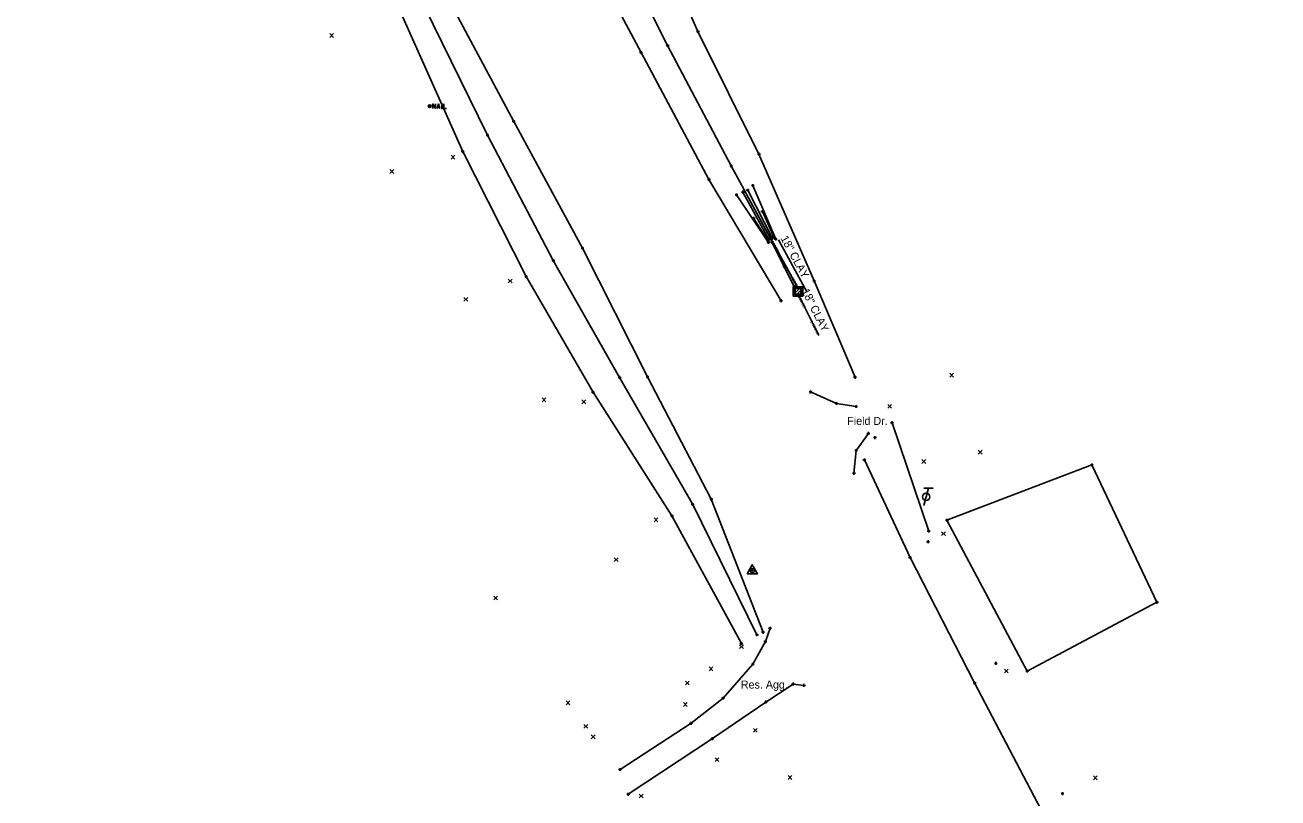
# Model space of a CAD drawing. Extents: x 2298098 to 2302860, y 557788 to 564251.
# Drawn here: x 2299686.7 to 2300125, y 560704.7 to 560975.2 of the extents above; entities that cross this region are included whole.
import ezdxf

# ---------------------------------------------------------------- set-up
doc = ezdxf.new("R2010")
doc.units = 0
for name, color, linetype in [('BD_X_Building', 7, 'Continuous'), ('DR_X_Cells', 7, 'Continuous'), ('DR_X_Ditch', 7, 'Continuous'), ('DR_X_Elev_Flow', 7, 'Continuous'), ('DR_X_Storm_Sewer', 7, 'Continuous'), ('DR_X_Text', 7, 'Continuous'), ('GK_Drainage_Nodes', 7, 'Continuous'), ('PV_X_Curb', 7, 'Continuous'), ('PV_X_Driveway', 7, 'Continuous'), ('PV_X_Text', 7, 'Continuous'), ('SC_Scratch1', 7, 'Continuous'), ('SV_P_Aerial_Targets', 7, 'Continuous'), ('SV_X_Break_Lines', 7, 'Continuous'), ('SV_X_Control_Cells_Found', 7, 'Continuous'), ('SV_X_Random_Point', 7, 'Continuous'), ('SV_X_Shot_Marker', 7, 'Continuous'), ('UT_X_Telecom_Cells', 7, 'Continuous')]:
    doc.layers.add(name, color=color, linetype=linetype)

msp = doc.modelspace()

# ---------------------------------------------------------------- linework, layer by layer
at = {"layer": 'BD_X_Building'}
msp.add_lwpolyline([(2300037.29, 560749.13), (2300082.72, 560773.18), (2300059.94, 560821.31), (2300009.23, 560801.93)], close=True, dxfattribs=at)
at = {"layer": 'DR_X_Cells'}
for p, q in [((2299955.98, 560881.35), (2299957.74, 560883.11)), ((2299955.98, 560882.48), (2299956.61, 560883.11)), ((2299956.58, 560880.82), (2299958.27, 560882.51)), ((2299957.71, 560880.82), (2299958.27, 560881.38))]:
    msp.add_line(p, q, dxfattribs=at)
for points in [[(2299955.46, 560883.63), (2299958.79, 560883.63), (2299958.79, 560880.3), (2299955.46, 560880.3)], [(2299955.98, 560883.11), (2299958.27, 560883.11), (2299958.27, 560880.82), (2299955.98, 560880.82)], [(2299956.13, 560882.96), (2299958.12, 560882.96), (2299958.12, 560880.97), (2299956.13, 560880.97)]]:
    msp.add_lwpolyline(points, close=True, dxfattribs=at)
at = {"layer": 'DR_X_Ditch'}
for p, q in [((2299946.86, 560900.2), (2299937.85, 560916.76)), ((2299939.52, 560917.42), (2299939.52, 560917.42)), ((2299948.12, 560900.69), (2299939.52, 560917.42))]:
    msp.add_line(p, q, dxfattribs=at)
for points in [[(2299947.33, 560900.77), (2299933.75, 560925.88), (2299911.49, 560968.04), (2299888.52, 561013.62), (2299864.88, 561059.66), (2299843.49, 561104.65), (2299821.62, 561147.64), (2299797.59, 561193.32), (2299770.88, 561234.4), (2299749.36, 561272.5)], [(2299689.17, 561239.02), (2299710.05, 561199.51), (2299732.46, 561156.76), (2299754.64, 561114.4), (2299777.04, 561070.1), (2299803.82, 561025.63), (2299826.29, 560981.81), (2299848.46, 560936.68), (2299871.48, 560892.79), (2299894.72, 560851.89), (2299920.28, 560807.43), (2299942.76, 560761.82)], [(2299955.8, 560883.68), (2299947.98, 560899.25)]]:
    msp.add_lwpolyline(points, dxfattribs=at)
at = {"layer": 'DR_X_Elev_Flow'}
for p, q in [((2299947.19, 560900.31), (2299948.19, 560900.31)), ((2299947.69, 560900.81), (2299947.69, 560899.81)), ((2299947.69, 560900.31), (2299947.69, 560900.31)), ((2299951.76, 560890.74), (2299952.76, 560890.74)), ((2299952.26, 560891.24), (2299952.26, 560890.24)), ((2299952.26, 560890.74), (2299952.26, 560890.74))]:
    msp.add_line(p, q, dxfattribs=at)
at = {"layer": 'DR_X_Storm_Sewer'}
for p, q in [((2299947.69, 560900.31), (2299957.12, 560882.96)), ((2299957.12, 560880.97), (2299964.37, 560866.53))]:
    msp.add_line(p, q, dxfattribs=at)
at = {"layer": 'DR_X_Text'}
msp.add_line((2299960.21, 560881.79), (2299950.29, 560900.02), dxfattribs=at)
at = {"layer": 'GK_Drainage_Nodes'}
for p, q in [((2299957.12, 560883.63), (2299957.12, 560883.63)), ((2299956.13, 560881.96), (2299956.13, 560881.96)), ((2299957.12, 560882.96), (2299957.12, 560882.96)), ((2299957.12, 560881.96), (2299957.12, 560881.96)), ((2299957.12, 560881.96), (2299957.12, 560881.96)), ((2299957.12, 560881.96), (2299957.12, 560881.96)), ((2299957.12, 560880.97), (2299957.12, 560880.97)), ((2299957.12, 560880.3), (2299957.12, 560880.3)), ((2299958.12, 560881.96), (2299958.12, 560881.96))]:
    msp.add_line(p, q, dxfattribs=at)
at = {"layer": 'PV_X_Curb'}
msp.add_line((2299935.62, 560915.79), (2299935.62, 560915.79), dxfattribs=at)
for points in [[(2299941.3, 560919.05), (2299949.32, 560900.24)], [(2299946.77, 560899.11), (2299935.62, 560915.79)]]:
    msp.add_lwpolyline(points, dxfattribs=at)
at = {"layer": 'PV_X_Driveway'}
for points in [[(2299961.53, 560846.8), (2299970.58, 560842.74), (2299977.47, 560841.68)], [(2299976.68, 560818.33), (2299977.47, 560826.3), (2299981.76, 560832.31)], [(2299947.34, 560764.07), (2299945.7, 560759.43), (2299941.3, 560751.53), (2299930.9, 560739.64), (2299919.71, 560730.84), (2299894.85, 560714.65)], [(2299897.73, 560706.01), (2299927.17, 560725.49), (2299945.85, 560738.28), (2299955.39, 560744.58), (2299959.21, 560744.09)]]:
    msp.add_lwpolyline(points, dxfattribs=at)
at = {"layer": 'SV_P_Aerial_Targets'}
msp.add_lwpolyline([(2299939.32, 560783.09), (2299942.92, 560783.09), (2299941.12, 560786.31)], close=True, dxfattribs=at)
for radius in [0.7, 0.16]:
    msp.add_circle((2299941.12, 560784.25), radius, dxfattribs=at)
at = {"layer": 'SV_X_Break_Lines'}
for points in [[(2299977.08, 560851.92), (2299962.79, 560885.63), (2299943.44, 560930.04), (2299922.12, 560972.96), (2299899.62, 561024.1), (2299876.86, 561061.88), (2299856.06, 561110.09), (2299831.14, 561154.42), (2299808.16, 561196.66), (2299781, 561237.26), (2299752.42, 561274.51)], [(2299743.18, 561269.26), (2299761.95, 561229.81), (2299785.6, 561185.67), (2299809.04, 561141.23), (2299831.82, 561097.39), (2299855.54, 561053.53), (2299878.79, 561009.46), (2299902.19, 560965.55), (2299925.95, 560921.19), (2299951.18, 560878.72)], [(2299692.06, 561241.01), (2299717.5, 561205.23), (2299740.15, 561162.59), (2299763.02, 561119.04), (2299785.96, 561075.58), (2299810.78, 561030.53), (2299833.61, 560986.47), (2299857.66, 560941.45), (2299881.73, 560897.12), (2299904.47, 560852.04), (2299926.78, 560809.23), (2299944.9, 560762.68)], [(2299937.32, 560758.74), (2299913.01, 560803.44), (2299885.4, 560846.69), (2299862.02, 560887.18), (2299839.82, 560930.89), (2299818.82, 560977.94), (2299795.83, 561022.36), (2299768.22, 561073.24), (2299750.41, 561112.94), (2299723.48, 561156), (2299704.62, 561197.18), (2299686.67, 561238.25)], [(2299948.81, 560900.74), (2299944.67, 560909.91)], [(2299946.68, 560899.68), (2299941.59, 560907.59)], [(2300002.85, 560798.07), (2299990.04, 560836.02)], [(2299980.36, 560823), (2299996.31, 560788.88), (2300018.92, 560744.96), (2300042.25, 560700.52), (2300065.09, 560656.83), (2300088.55, 560612.83), (2300119.49, 560571.33), (2300125.05, 560565.91)]]:
    msp.add_lwpolyline(points, dxfattribs=at)
at = {"layer": 'SV_X_Control_Cells_Found'}
for p, q in [((2299827.92, 560947.16), (2299828.62, 560946.45)), ((2299827.92, 560946.45), (2299828.62, 560947.16))]:
    msp.add_line(p, q, dxfattribs=at)
for points in [[(2299829.36, 560946), (2299829.36, 560947.6), (2299830.3, 560946), (2299830.3, 560947.6)], [(2299830.81, 560946), (2299831.31, 560947.6), (2299831.8, 560946)], [(2299831.68, 560946.38), (2299830.93, 560946.38)], [(2299832.31, 560947.6), (2299832.71, 560947.6)], [(2299832.31, 560946), (2299832.71, 560946)], [(2299832.51, 560946), (2299832.51, 560947.6)], [(2299833.21, 560947.6), (2299833.21, 560946), (2299834.08, 560946)]]:
    msp.add_lwpolyline(points, dxfattribs=at)
msp.add_circle((2299828.27, 560946.81), 0.5, dxfattribs=at)
at = {"layer": 'SV_X_Random_Point'}
for p, q in [((2299793.28, 560970.88), (2299794.61, 560972.21)), ((2299793.28, 560972.21), (2299794.61, 560970.88)), ((2299835.71, 560928.28), (2299837.04, 560929.61)), ((2299835.71, 560929.61), (2299837.04, 560928.28)), ((2299814.32, 560923.27), (2299815.65, 560924.6)), ((2299814.32, 560924.6), (2299815.65, 560923.27)), ((2299855.76, 560884.94), (2299857.09, 560886.27)), ((2299855.76, 560886.27), (2299857.09, 560884.94)), ((2299840.23, 560878.56), (2299841.56, 560879.89)), ((2299840.23, 560879.89), (2299841.56, 560878.56)), ((2300010.22, 560851.98), (2300011.55, 560853.31)), ((2300010.22, 560853.31), (2300011.55, 560851.98)), ((2299867.58, 560843.36), (2299868.91, 560844.7)), ((2299867.58, 560844.7), (2299868.91, 560843.36)), ((2299881.52, 560842.69), (2299882.85, 560844.02)), ((2299881.52, 560844.02), (2299882.85, 560842.69)), ((2299988.51, 560841.09), (2299989.84, 560842.42)), ((2299988.51, 560842.42), (2299989.84, 560841.09)), ((2300000.48, 560821.78), (2300001.81, 560823.12)), ((2300000.48, 560823.12), (2300001.81, 560821.78)), ((2300020.2, 560825.06), (2300021.54, 560826.4)), ((2300020.2, 560826.4), (2300021.54, 560825.06)), ((2299906.76, 560801.37), (2299908.09, 560802.7)), ((2299906.76, 560802.7), (2299908.09, 560801.37)), ((2300007.36, 560796.54), (2300008.69, 560797.88)), ((2300007.36, 560797.88), (2300008.69, 560796.54)), ((2299892.85, 560787.44), (2299894.18, 560788.77)), ((2299892.85, 560788.77), (2299894.18, 560787.44)), ((2299850.65, 560774.04), (2299851.98, 560775.38)), ((2299850.65, 560775.38), (2299851.98, 560774.04)), ((2299936.7, 560756.97), (2299938.03, 560758.3)), ((2299936.7, 560758.3), (2299938.03, 560756.97)), ((2299926, 560749.25), (2299927.33, 560750.59)), ((2299926, 560750.59), (2299927.33, 560749.25)), ((2300029.33, 560748.46), (2300030.67, 560749.79)), ((2300029.33, 560749.79), (2300030.67, 560748.46)), ((2299917.72, 560744.29), (2299919.06, 560745.62)), ((2299917.72, 560745.62), (2299919.06, 560744.29)), ((2299875.99, 560737.31), (2299877.32, 560738.64)), ((2299875.99, 560738.64), (2299877.32, 560737.31)), ((2299917.03, 560736.74), (2299918.36, 560738.07)), ((2299917.03, 560738.07), (2299918.36, 560736.74)), ((2299882.2, 560729.11), (2299883.53, 560730.45)), ((2299882.2, 560730.45), (2299883.53, 560729.11)), ((2299884.75, 560725.45), (2299886.09, 560726.78)), ((2299884.75, 560726.78), (2299886.09, 560725.45)), ((2299941.53, 560727.72), (2299942.86, 560729.06)), ((2299941.53, 560729.06), (2299942.86, 560727.72)), ((2299928.08, 560717.41), (2299929.41, 560718.74)), ((2299928.08, 560718.74), (2299929.41, 560717.41)), ((2299953.63, 560711.19), (2299954.96, 560712.53)), ((2299953.63, 560712.53), (2299954.96, 560711.19)), ((2300060.49, 560711.07), (2300061.82, 560712.4)), ((2300060.49, 560712.4), (2300061.82, 560711.07)), ((2299901.57, 560704.75), (2299902.91, 560706.08)), ((2299901.57, 560706.08), (2299902.91, 560704.75))]:
    msp.add_line(p, q, dxfattribs=at)
at = {"layer": 'SV_X_Shot_Marker'}
for p, q in [((2299921.62, 560972.96), (2299922.62, 560972.96)), ((2299922.12, 560973.46), (2299922.12, 560972.46)), ((2299922.12, 560972.96), (2299922.12, 560972.96)), ((2299910.99, 560968.04), (2299911.99, 560968.04)), ((2299911.49, 560968.54), (2299911.49, 560967.54)), ((2299911.49, 560968.04), (2299911.49, 560968.04)), ((2299901.69, 560965.55), (2299902.69, 560965.55)), ((2299902.19, 560966.05), (2299902.19, 560965.05)), ((2299902.19, 560965.55), (2299902.19, 560965.55)), ((2299857.16, 560941.45), (2299858.16, 560941.45)), ((2299857.66, 560941.95), (2299857.66, 560940.95)), ((2299857.66, 560941.45), (2299857.66, 560941.45)), ((2299847.96, 560936.68), (2299848.96, 560936.68)), ((2299848.46, 560937.18), (2299848.46, 560936.18)), ((2299848.46, 560936.68), (2299848.46, 560936.68)), ((2299839.32, 560930.89), (2299840.32, 560930.89)), ((2299839.82, 560931.39), (2299839.82, 560930.39)), ((2299839.82, 560930.89), (2299839.82, 560930.89)), ((2299942.94, 560930.04), (2299943.94, 560930.04)), ((2299943.44, 560930.54), (2299943.44, 560929.54)), ((2299943.44, 560930.04), (2299943.44, 560930.04)), ((2299933.25, 560925.88), (2299934.25, 560925.88)), ((2299933.75, 560926.38), (2299933.75, 560925.38)), ((2299933.75, 560925.88), (2299933.75, 560925.88)), ((2299925.45, 560921.19), (2299926.45, 560921.19)), ((2299925.95, 560921.69), (2299925.95, 560920.69)), ((2299925.95, 560921.19), (2299925.95, 560921.19)), ((2299940.8, 560919.05), (2299941.8, 560919.05)), ((2299941.3, 560919.55), (2299941.3, 560918.55)), ((2299941.3, 560919.05), (2299941.3, 560919.05)), ((2299935.12, 560915.79), (2299936.12, 560915.79)), ((2299935.62, 560916.29), (2299935.62, 560915.29)), ((2299935.62, 560915.79), (2299935.62, 560915.79)), ((2299937.35, 560916.76), (2299938.35, 560916.76)), ((2299937.85, 560917.26), (2299937.85, 560916.26)), ((2299937.85, 560916.76), (2299937.85, 560916.76)), ((2299939.02, 560917.42), (2299940.02, 560917.42)), ((2299939.52, 560917.92), (2299939.52, 560916.92)), ((2299939.52, 560917.42), (2299939.52, 560917.42)), ((2299944.17, 560909.91), (2299945.17, 560909.91)), ((2299944.67, 560910.41), (2299944.67, 560909.41)), ((2299944.67, 560909.91), (2299944.67, 560909.91)), ((2299941.09, 560907.59), (2299942.09, 560907.59)), ((2299941.59, 560908.09), (2299941.59, 560907.09)), ((2299941.59, 560907.59), (2299941.59, 560907.59)), ((2299947.33, 560901.27), (2299947.33, 560900.27)), ((2299948.12, 560901.19), (2299948.12, 560900.19)), ((2299948.81, 560901.24), (2299948.81, 560900.24)), ((2299881.23, 560897.12), (2299882.23, 560897.12)), ((2299881.73, 560897.62), (2299881.73, 560896.62)), ((2299881.73, 560897.12), (2299881.73, 560897.12)), ((2299946.18, 560899.68), (2299947.18, 560899.68)), ((2299946.27, 560899.11), (2299947.27, 560899.11)), ((2299946.36, 560900.2), (2299947.36, 560900.2)), ((2299946.68, 560900.18), (2299946.68, 560899.18)), ((2299946.68, 560899.68), (2299946.68, 560899.68)), ((2299946.77, 560899.61), (2299946.77, 560898.61)), ((2299946.77, 560899.11), (2299946.77, 560899.11)), ((2299946.83, 560900.77), (2299947.83, 560900.77)), ((2299946.86, 560900.7), (2299946.86, 560899.7)), ((2299946.86, 560900.2), (2299946.86, 560900.2)), ((2299947.33, 560900.77), (2299947.33, 560900.77)), ((2299947.48, 560899.25), (2299948.48, 560899.25)), ((2299947.62, 560900.69), (2299948.62, 560900.69)), ((2299947.98, 560899.75), (2299947.98, 560898.75)), ((2299947.98, 560899.25), (2299947.98, 560899.25)), ((2299948.12, 560900.69), (2299948.12, 560900.69)), ((2299948.31, 560900.74), (2299949.31, 560900.74)), ((2299948.81, 560900.74), (2299948.81, 560900.74)), ((2299948.82, 560900.24), (2299949.82, 560900.24)), ((2299949.32, 560900.74), (2299949.32, 560899.74)), ((2299949.32, 560900.24), (2299949.32, 560900.24)), ((2299870.98, 560892.79), (2299871.98, 560892.79)), ((2299871.48, 560893.29), (2299871.48, 560892.29)), ((2299871.48, 560892.79), (2299871.48, 560892.79)), ((2299861.52, 560887.18), (2299862.52, 560887.18)), ((2299862.02, 560887.68), (2299862.02, 560886.68)), ((2299862.02, 560887.18), (2299862.02, 560887.18)), ((2299955.3, 560883.68), (2299956.3, 560883.68)), ((2299955.8, 560884.18), (2299955.8, 560883.18)), ((2299955.8, 560883.68), (2299955.8, 560883.68)), ((2299962.29, 560885.63), (2299963.29, 560885.63)), ((2299962.79, 560886.13), (2299962.79, 560885.13)), ((2299962.79, 560885.63), (2299962.79, 560885.63)), ((2299951.18, 560879.22), (2299951.18, 560878.22)), ((2299950.68, 560878.72), (2299951.68, 560878.72)), ((2299951.18, 560878.72), (2299951.18, 560878.72)), ((2299894.22, 560851.89), (2299895.22, 560851.89)), ((2299894.72, 560852.39), (2299894.72, 560851.39)), ((2299894.72, 560851.89), (2299894.72, 560851.89)), ((2299903.97, 560852.04), (2299904.97, 560852.04)), ((2299904.47, 560852.54), (2299904.47, 560851.54)), ((2299904.47, 560852.04), (2299904.47, 560852.04)), ((2299976.58, 560851.92), (2299977.58, 560851.92)), ((2299977.08, 560852.42), (2299977.08, 560851.42)), ((2299977.08, 560851.92), (2299977.08, 560851.92)), ((2299884.9, 560846.69), (2299885.9, 560846.69)), ((2299885.4, 560847.19), (2299885.4, 560846.19)), ((2299885.4, 560846.69), (2299885.4, 560846.69)), ((2299961.03, 560846.8), (2299962.03, 560846.8)), ((2299961.53, 560847.3), (2299961.53, 560846.3)), ((2299961.53, 560846.8), (2299961.53, 560846.8)), ((2299970.08, 560842.74), (2299971.08, 560842.74)), ((2299970.58, 560843.24), (2299970.58, 560842.24)), ((2299970.58, 560842.74), (2299970.58, 560842.74)), ((2299976.97, 560841.68), (2299977.97, 560841.68)), ((2299977.47, 560842.18), (2299977.47, 560841.18)), ((2299977.47, 560841.68), (2299977.47, 560841.68)), ((2299989.54, 560836.02), (2299990.54, 560836.02)), ((2299990.04, 560836.52), (2299990.04, 560835.52)), ((2299990.04, 560836.02), (2299990.04, 560836.02)), ((2299981.26, 560832.31), (2299982.26, 560832.31)), ((2299981.76, 560832.81), (2299981.76, 560831.81)), ((2299981.76, 560832.31), (2299981.76, 560832.31)), ((2299984.05, 560831.32), (2299984.05, 560830.32)), ((2299977.47, 560826.8), (2299977.47, 560825.8)), ((2299983.55, 560830.82), (2299984.55, 560830.82)), ((2299984.05, 560830.82), (2299984.05, 560830.82)), ((2299976.97, 560826.3), (2299977.97, 560826.3)), ((2299977.47, 560826.3), (2299977.47, 560826.3)), ((2299979.86, 560823), (2299980.86, 560823)), ((2299980.36, 560823.5), (2299980.36, 560822.5)), ((2299980.36, 560823), (2299980.36, 560823)), ((2299976.18, 560818.33), (2299977.18, 560818.33)), ((2299976.68, 560818.83), (2299976.68, 560817.83)), ((2299976.68, 560818.33), (2299976.68, 560818.33)), ((2300059.44, 560821.31), (2300060.44, 560821.31)), ((2300059.94, 560821.81), (2300059.94, 560820.81)), ((2300059.94, 560821.31), (2300059.94, 560821.31)), ((2299926.28, 560809.23), (2299927.28, 560809.23)), ((2299926.78, 560809.73), (2299926.78, 560808.73)), ((2299926.78, 560809.23), (2299926.78, 560809.23)), ((2299919.78, 560807.43), (2299920.78, 560807.43)), ((2299920.28, 560807.93), (2299920.28, 560806.93)), ((2299920.28, 560807.43), (2299920.28, 560807.43)), ((2299912.51, 560803.44), (2299913.51, 560803.44)), ((2299913.01, 560803.94), (2299913.01, 560802.94)), ((2299913.01, 560803.44), (2299913.01, 560803.44)), ((2300008.73, 560801.93), (2300009.73, 560801.93)), ((2300009.23, 560802.43), (2300009.23, 560801.43)), ((2300009.23, 560801.93), (2300009.23, 560801.93)), ((2300002.35, 560798.07), (2300003.35, 560798.07)), ((2300002.85, 560798.57), (2300002.85, 560797.57)), ((2300002.85, 560798.07), (2300002.85, 560798.07)), ((2300002.12, 560794.39), (2300003.12, 560794.39)), ((2300002.62, 560794.89), (2300002.62, 560793.89)), ((2300002.62, 560794.39), (2300002.62, 560794.39)), ((2299995.81, 560788.88), (2299996.81, 560788.88)), ((2299996.31, 560789.38), (2299996.31, 560788.38)), ((2299996.31, 560788.88), (2299996.31, 560788.88)), ((2300082.22, 560773.18), (2300083.22, 560773.18)), ((2300082.72, 560773.68), (2300082.72, 560772.68)), ((2300082.72, 560773.18), (2300082.72, 560773.18)), ((2299942.26, 560761.82), (2299943.26, 560761.82)), ((2299942.76, 560762.32), (2299942.76, 560761.32)), ((2299942.76, 560761.82), (2299942.76, 560761.82)), ((2299944.4, 560762.68), (2299945.4, 560762.68)), ((2299944.9, 560763.18), (2299944.9, 560762.18)), ((2299944.9, 560762.68), (2299944.9, 560762.68)), ((2299946.84, 560764.07), (2299947.84, 560764.07)), ((2299947.34, 560764.57), (2299947.34, 560763.57)), ((2299947.34, 560764.07), (2299947.34, 560764.07)), ((2299936.78, 560758.74), (2299937.78, 560758.74)), ((2299936.82, 560758.74), (2299937.82, 560758.74)), ((2299937.28, 560759.24), (2299937.28, 560758.24)), ((2299937.28, 560758.74), (2299937.28, 560758.74)), ((2299937.32, 560759.24), (2299937.32, 560758.24)), ((2299937.32, 560758.74), (2299937.32, 560758.74)), ((2299945.2, 560759.43), (2299946.2, 560759.43)), ((2299945.7, 560759.93), (2299945.7, 560758.93)), ((2299945.7, 560759.43), (2299945.7, 560759.43)), ((2299941.3, 560752.03), (2299941.3, 560751.03)), ((2300026.34, 560752.31), (2300026.34, 560751.31)), ((2299940.8, 560751.53), (2299941.8, 560751.53)), ((2299941.3, 560751.53), (2299941.3, 560751.53)), ((2300025.84, 560751.81), (2300026.84, 560751.81)), ((2300026.34, 560751.81), (2300026.34, 560751.81)), ((2300036.79, 560749.13), (2300037.79, 560749.13)), ((2300037.29, 560749.63), (2300037.29, 560748.63)), ((2300037.29, 560749.13), (2300037.29, 560749.13)), ((2299954.89, 560744.58), (2299955.89, 560744.58)), ((2299955.39, 560745.08), (2299955.39, 560744.08)), ((2299955.39, 560744.58), (2299955.39, 560744.58)), ((2299958.71, 560744.09), (2299959.71, 560744.09)), ((2299959.21, 560744.59), (2299959.21, 560743.59)), ((2299959.21, 560744.09), (2299959.21, 560744.09)), ((2300018.42, 560744.96), (2300019.42, 560744.96)), ((2300018.92, 560745.46), (2300018.92, 560744.46)), ((2300018.92, 560744.96), (2300018.92, 560744.96)), ((2299930.4, 560739.64), (2299931.4, 560739.64)), ((2299930.9, 560740.14), (2299930.9, 560739.14)), ((2299930.9, 560739.64), (2299930.9, 560739.64)), ((2299945.35, 560738.28), (2299946.35, 560738.28)), ((2299945.85, 560738.78), (2299945.85, 560737.78)), ((2299945.85, 560738.28), (2299945.85, 560738.28)), ((2299919.21, 560730.84), (2299920.21, 560730.84)), ((2299919.71, 560731.34), (2299919.71, 560730.34)), ((2299919.71, 560730.84), (2299919.71, 560730.84)), ((2299927.17, 560725.99), (2299927.17, 560724.99)), ((2299926.67, 560725.49), (2299927.67, 560725.49)), ((2299927.17, 560725.49), (2299927.17, 560725.49)), ((2299894.35, 560714.65), (2299895.35, 560714.65)), ((2299894.85, 560715.15), (2299894.85, 560714.15)), ((2299894.85, 560714.65), (2299894.85, 560714.65)), ((2299897.23, 560706.01), (2299898.23, 560706.01)), ((2299897.73, 560706.51), (2299897.73, 560705.51)), ((2299897.73, 560706.01), (2299897.73, 560706.01)), ((2300049.18, 560706.22), (2300050.18, 560706.22)), ((2300049.68, 560706.72), (2300049.68, 560705.72)), ((2300049.68, 560706.22), (2300049.68, 560706.22))]:
    msp.add_line(p, q, dxfattribs=at)
at = {"layer": 'UT_X_Telecom_Cells'}
for p, q in [((2300002.77, 560813.09), (2300001.16, 560807.09)), ((2300004.37, 560813.09), (2300001.17, 560813.09))]:
    msp.add_line(p, q, dxfattribs=at)
msp.add_circle((2300001.96, 560810.09), 1.3, dxfattribs=at)

# ---------------------------------------------------------------- texts
at = {"layer": 'DR_X_Text'}
for rotation, p in [(298.5445, (2299950.92, 560900.6)), (298.5445, (2299950.92, 560900.6)), (296.6574, (2299958.3, 560882.12))]:
    msp.add_text('18" CLAY', height=2.8, rotation=rotation, dxfattribs=at).set_placement(p)
at = {"layer": 'PV_X_Text'}
for s, p in [('Field Dr.', (2299974.36, 560835.25)), ('Res. Agg.', (2299937.12, 560742.99))]:
    msp.add_text(s, height=2.8, dxfattribs=at).set_placement(p)
at = {"layer": 'SC_Scratch1'}
for s, rotation, p in [("1110.32'", 298.5445, (2299947.25, 560900.07)), ("1,106.55'", 298.5445, (2299953.92, 560887.82)), ("1106.05'", 296.6574, (2299956.68, 560880.74)), ("1,106.05'", 296.6574, (2299961.33, 560871.48))]:
    msp.add_text(s, height=1, rotation=rotation, dxfattribs=at).set_placement(p)

doc.saveas('drawing.dxf')
